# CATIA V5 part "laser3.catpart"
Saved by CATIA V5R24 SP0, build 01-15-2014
Part number: Part2
Bounding box of the stored display mesh (mm): x 0 to 10, y 0 to 18.55, z 0 to 21.05
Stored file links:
  C:\Users\183630\Desktop\Laser3.CATPart
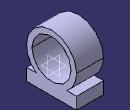
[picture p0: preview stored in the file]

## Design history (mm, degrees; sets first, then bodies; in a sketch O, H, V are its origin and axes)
Body1 (main body)
  Sketch1 on yz-plane, origin (0, 0, 0), H (0, 1, 0), V (0, 0, 1)
    arc A1 centre (9.275, 11.775) radius 9.275 from (3.5801, 4.4542) to (14.9699, 4.4542) ccw
    line L1 (18.55, 4.4542) -> (18.55, 0)
    point P2 (18.55, 0)
    line L2 (18.55, 0) -> (0, 0)
    line L3 (0, 0) -> (0, 4.4542)
    line L4 (18.55, 4.4542) -> (14.9699, 4.4542)
    point P5 (3.5801, 4.4542)
    line L5 (3.5801, 4.4542) -> (0, 4.4542)
    radius A1 = 9.275
    distance A1 H = 2.5
    length L4 = 3.5801
    length L5 = 3.5801
    tangency: A1 V, L1 A1, L3 A1
    coincidence: P2 H, P5 L4
    horizontal: L2 H, L4 H, L5 H
  Pad1: profile Sketch1, direction (1, 0, 0), length 10
  Sketch2 on end face of Pad1, origin (10, 0, 0), H (0, 1, 0), V (0, 0, 1)
    circle A1 centre (9.275, 11.775) radius 9.275
    point P1 (9.275, 11.775)
    reference projected arc E1 centre (9.275, 11.775) radius 9.275 from (3.5801, 4.4542) to (14.9699, 4.4542) ccw from edge [face of Pad1 from Sketch1.A1 | end face of Pad1]
    distance P1 V = 9.275
    radius A1 = 9.275
    tangency: A1 E1
  Pad2: profile Sketch2, direction (-1, 0, 0), length 10
  Sketch3 on face of Pad2, origin (10, 0, 0), H (0, 1, 0), V (0, 0, 1)
    circle A1 centre (9.275, 11.775) radius 7.275
    point P1 (9.275, 11.775)
    reference projected circle E1 centre (9.275, 11.775) radius 9.275 from edge [face of Pad2 from Sketch2.A1 | start face of Pad2]
    reference projected line E2 (18.55, 4.4542) -> (14.9699, 4.4542) from edge [face of Pad1 from Sketch1.L4 | face of Pad2]
    radius A1 = 7.275
    distance P1 V = 9.275
    distance E1 E2 = 16.5958 (reference)
    distance H P1 = 11.775
  Pocket1: profile Sketch3, direction (-1, 0, 0), length 10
